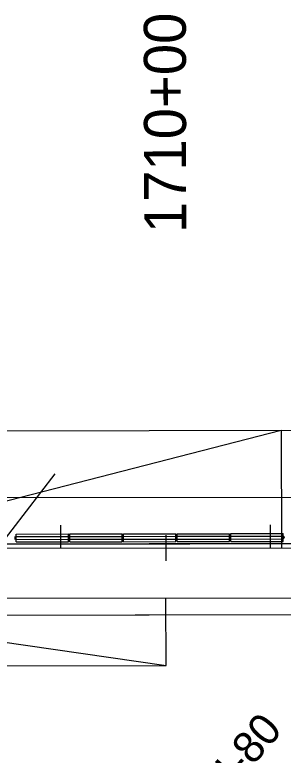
# Model space of a CAD drawing. Extents: x 16513048 to 16518780, y 7009856 to 7010869.
# Drawn here: x 16515704.8 to 16515768.8, y 7010308.2 to 7010484.6 of the extents above; entities that cross this region are included whole.
import ezdxf

# ---------------------------------------------------------------- set-up
doc = ezdxf.new("R2010")
doc.units = 0
for name, color, linetype in [('Dimensions', 7, 'Continuous'), ('dsnCellElements', 7, 'Continuous'), ('dsnNonPlotable', 7, 'Continuous'), ('EdgePaved', 7, 'Continuous'), ('Shape', 7, 'Continuous'), ('SheetBorder', 7, 'Continuous'), ('tdCoTitleBlock', 7, 'Continuous')]:
    doc.layers.add(name, color=color, linetype=linetype)

msp = doc.modelspace()

# ---------------------------------------------------------------- linework, layer by layer
at = {"layer": 'dsnCellElements'}
for p, q in [((16515756.29, 7010361.01), (16515768.79, 7010361.03)), ((16515768.79, 7010359.15), (16515768.79, 7010361.03)), ((16515705.08, 7010360.92), (16515717.58, 7010360.94)), ((16515705.08, 7010359.04), (16515705.08, 7010360.92)), ((16515705.08, 7010360.32), (16515717.58, 7010360.34)), ((16515705.08, 7010359.64), (16515717.58, 7010359.66)), ((16515717.58, 7010359.06), (16515717.58, 7010360.94)), ((16515717.88, 7010360.94), (16515730.38, 7010360.96)), ((16515717.88, 7010359.06), (16515717.88, 7010360.94)), ((16515717.88, 7010360.34), (16515730.38, 7010360.36)), ((16515717.88, 7010359.66), (16515730.38, 7010359.69)), ((16515730.38, 7010359.09), (16515730.38, 7010360.96)), ((16515730.68, 7010360.96), (16515743.18, 7010360.98)), ((16515730.69, 7010359.09), (16515730.68, 7010360.96)), ((16515730.68, 7010360.36), (16515743.18, 7010360.38)), ((16515730.68, 7010359.69), (16515743.19, 7010359.71)), ((16515743.19, 7010359.11), (16515743.18, 7010360.98)), ((16515743.48, 7010360.98), (16515755.98, 7010361)), ((16515743.49, 7010359.11), (16515743.48, 7010360.98)), ((16515743.49, 7010360.38), (16515755.99, 7010360.4)), ((16515743.49, 7010359.71), (16515755.99, 7010359.73)), ((16515755.99, 7010359.13), (16515755.98, 7010361)), ((16515756.29, 7010359.13), (16515756.29, 7010361.01)), ((16515756.29, 7010360.41), (16515768.79, 7010360.43)), ((16515756.29, 7010359.73), (16515768.79, 7010359.75)), ((16515705.08, 7010359.04), (16515717.58, 7010359.06)), ((16515717.88, 7010359.06), (16515730.38, 7010359.09)), ((16515730.69, 7010359.09), (16515743.19, 7010359.11)), ((16515743.49, 7010359.11), (16515755.99, 7010359.13)), ((16515756.29, 7010359.13), (16515768.79, 7010359.15))]:
    msp.add_line(p, q, dxfattribs=at)
at = {"layer": 'dsnNonPlotable'}
for p, q in [((16515658.39, 7010357.46), (16515768.34, 7010385.65)), ((16515768.34, 7010385.65), (16515768.39, 7010357.65)), ((16513050.27, 7010352.91), (16516699.62, 7010359.27)), ((16515630.83, 7010345.41), (16515740.86, 7010329.6)), ((16515740.86, 7010329.6), (16515740.83, 7010345.6)), ((16513050.32, 7010324.91), (16515740.86, 7010329.6))]:
    msp.add_line(p, q, dxfattribs=at)
for points in [[(16513050.22, 7010380.91), (16516699.59, 7010387.27), (16518770.65, 7010388.94)], [(16518770.66, 7010372.94), (16516699.61, 7010371.27), (16513050.25, 7010364.91)], [(16518770.68, 7010348.94), (16516699.64, 7010347.27), (16513050.29, 7010340.91)], [(16518770.69, 7010344.94), (16516699.64, 7010343.27), (16513050.3, 7010336.91)]]:
    msp.add_lwpolyline(points, dxfattribs=at)
at = {"layer": 'EdgePaved'}
msp.add_line((16515714.33, 7010375.22), (16515687.07, 7010339.84), dxfattribs=at)
for centre in [(16515704.93, 7010359.98), (16515704.93, 7010359.98), (16515717.73, 7010360), (16515717.73, 7010360), (16515730.53, 7010360.02), (16515730.53, 7010360.02), (16515743.34, 7010360.05), (16515743.34, 7010360.05), (16515756.14, 7010360.07), (16515756.14, 7010360.07)]:
    msp.add_circle(centre, 0.0521, dxfattribs=at)
for centre, start, end in [((16515704.78, 7010359.98), 270.0999, 90.0999), ((16515705.08, 7010359.98), 90.0999, 270.0999), ((16515717.58, 7010360), 270.0999, 90.0999), ((16515717.88, 7010360), 90.0999, 270.0999), ((16515730.38, 7010360.02), 270.0999, 90.0999), ((16515730.68, 7010360.02), 90.0999, 270.0999), ((16515743.18, 7010360.04), 270.0999, 90.0999), ((16515743.49, 7010360.05), 90.0999, 270.0999), ((16515755.99, 7010360.07), 270.0999, 90.0999), ((16515756.29, 7010360.07), 90.0999, 270.0999), ((16515768.79, 7010360.09), 270.0999, 90.0999)]:
    msp.add_arc(centre, 0.281, start, end, dxfattribs=at)
at = {"layer": 'Shape'}
msp.add_line((16516114.45, 7010359.25), (16515602.67, 7010358.36), dxfattribs=at)
msp.add_lwpolyline([(16516017.16, 7010359.09), (16516004.05, 7010342.06), (16515688.36, 7010341.51), (16515701.47, 7010358.53), (16516017.16, 7010359.09)], close=True, dxfattribs=at)
at = {"layer": 'SheetBorder'}
for p, q in [((16515715.79, 7010357.56), (16515715.78, 7010363.02)), ((16515765.79, 7010357.65), (16515765.78, 7010363.11)), ((16515740.78, 7010360.66), (16515740.8, 7010354.54))]:
    msp.add_line(p, q, dxfattribs=at)
at = {"layer": 'tdCoTitleBlock'}
msp.add_line((16515740.78, 7010360.66), (16515740.8, 7010354.54), dxfattribs=at)

# ---------------------------------------------------------------- texts
at = {"layer": 'Dimensions'}
msp.add_text('WB I-80', height=7.5, rotation=49.1804, dxfattribs=at).set_placement((16515745.21, 7010286.65))
at = {"layer": 'SheetBorder'}
msp.add_text('1710+00', height=10.02, rotation=90.0999, dxfattribs=at).set_placement((16515745.67, 7010432.61))
at = {"layer": 'tdCoTitleBlock'}
msp.add_text('1710+00', height=10.02, rotation=90.0999, dxfattribs=at).set_placement((16515745.67, 7010432.61))

doc.saveas('drawing.dxf')
